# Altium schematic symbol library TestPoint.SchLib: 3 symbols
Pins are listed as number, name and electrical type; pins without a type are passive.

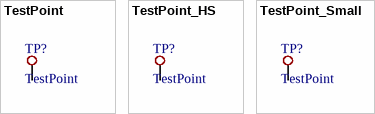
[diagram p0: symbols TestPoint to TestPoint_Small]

## TestPoint
designator TP?
footprint TP_50mil
pins: 1

## TestPoint_HS
designator TP?, comment TestPoint
footprint TP_HS
pins: 1

## TestPoint_Small
designator TP?, comment TestPoint
footprint TP_0.5
pins: 1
